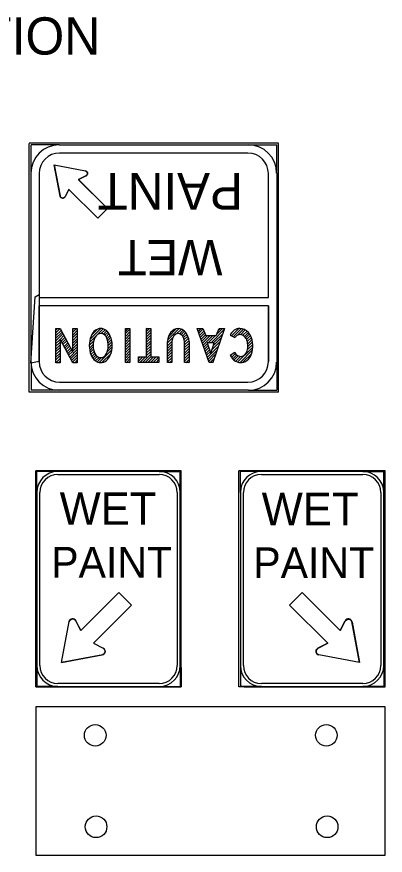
# Model space of a CAD drawing. Extents: x 1531.94 to 1538.58, y 1529.59 to 1539.32.
# Drawn here: x 1536.631 to 1537.698, y 1536.89 to 1539.32 of the extents above; entities that cross this region are included whole.
import ezdxf

# ---------------------------------------------------------------- set-up
doc = ezdxf.new("R2010")
doc.units = 0
for name, color, linetype in [('DETL-LINE', 7, 'Continuous'), ('DETL-TITL', 7, 'Continuous'), ('USER-BORD', 7, 'Continuous')]:
    doc.layers.add(name, color=color, linetype=linetype)

# ---------------------------------------------------------------- blocks, each defined once
blk = doc.blocks.new('EBK780')
at = {"layer": 'USER-BORD'}
blk.add_lwpolyline([(1.5, 0), (0.39, 1.65), (0.39, 0), (0, 0), (0, 2.4), (0.39, 2.4), (1.5, 0.75), (1.5, 2.4), (1.89, 2.4), (1.89, 0)], close=True, dxfattribs=at)
blk = doc.blocks.new('EBK790')
at = {"layer": 'USER-BORD'}
for centre, radius, start, end in [((1, 1.451), 0.943, 26.05051, 153.94949), ((1.477, 1.193), 1.484, 153.11255, 206.88745), ((1, 1.451), 0.593, 30.87343, 149.12656), ((0.523, 1.193), 1.484, 333.11255, 26.88745), ((1.477, 1.193), 1.134, 150.33396, 206.88745), ((0.523, 1.193), 1.134, 330.33396, 29.66604), ((1, 0.936), 0.593, 206.05051, 329.12657), ((1, 0.936), 0.943, 206.05051, 333.94949)]:
    blk.add_arc(centre, radius, start, end, dxfattribs=at)
blk = doc.blocks.new('EBK730')
at = {"layer": 'USER-BORD'}
blk.add_lwpolyline([(0.3996, 2.3977), (0.3996, 0), (0, 0), (0, 2.3977)], close=True, dxfattribs=at)
blk = doc.blocks.new('EBK840')
at = {"layer": 'USER-BORD'}
blk.add_lwpolyline([(1.1024, -0.0068), (0.7028, -0.0068), (0.7028, 1.9913), (0.0026, 1.9913), (0.0026, 2.3909), (1.8026, 2.3909), (1.8026, 1.9913), (1.1024, 1.9913)], close=True, dxfattribs=at)
blk = doc.blocks.new('EBK850')
at = {"layer": 'USER-BORD'}
for points in [[(0.001, 0.9), (0.001, 2.398), (0.401, 2.398), (0.401, 0.9)], [(1.501, 0.9), (1.501, 2.398), (1.901, 2.398), (1.901, 0.9)]]:
    blk.add_lwpolyline(points, dxfattribs=at)
for centre, radius, start, end in [((0.951, 0.951), 0.951, 183.08456, 356.91544), ((0.951, 0.9), 0.55, 180, 0)]:
    blk.add_arc(centre, radius, start, end, dxfattribs=at)
blk = doc.blocks.new('EBK650')
at = {"layer": 'USER-BORD'}
blk.add_lwpolyline([(1.6744, 0.479), (0.7349, 0.479), (0.4957, 0), (0, 0), (1.0352, 2.3825), (1.3681, 2.3825), (2.4033, 0), (1.9076, 0), (1.6684, 0.479)], dxfattribs=at)
blk.add_lwpolyline([(1.2017, 1.7541), (0.9085, 0.9938), (1.5306, 0.9938)], close=True, dxfattribs=at)
blk = doc.blocks.new('EBK670')
at = {"layer": 'USER-BORD'}
for p, q in [((1.582, 1.676), (1.964, 1.888)), ((1.981, 0.462), (1.569, 0.631)), ((1.981, 0.462), (1.981, 0.462))]:
    blk.add_line(p, q, dxfattribs=at)
for centre, radius, start, end in [((1.058, 1.338), 1.06, 31.25658, 163.71904), ((1.058, 1.338), 0.623, 32.82084, 158.25313), ((2.007, 1.189), 2.016, 167.21329, 185.68444), ((1.445, 1.229), 1.023, 160.60471, 209.69376), ((1.124, 1.121), 1.131, 186.67975, 270.86337), ((1.124, 1.121), 0.695, 215.04405, 285.81135), ((1.148, 0.961), 0.535, 288.00465, 321.8072), ((1.148, 0.961), 0.971, 269.58816, 329.07561)]:
    blk.add_arc(centre, radius, start, end, dxfattribs=at)

msp = doc.modelspace()

# ---------------------------------------------------------------- linework, layer by layer
at = {"layer": 'DETL-LINE'}
for p, q in [((1537.3887, 1538.9543), (1536.6672, 1538.9543)), ((1536.6672, 1538.2329), (1536.6672, 1538.953)), ((1536.754, 1538.949), (1536.6725, 1538.949)), ((1536.6725, 1538.8675), (1536.6725, 1538.949)), ((1536.754, 1538.949), (1537.3019, 1538.949)), ((1537.3019, 1538.949), (1537.3838, 1538.949)), ((1537.3838, 1538.8675), (1537.3838, 1538.949)), ((1537.3887, 1538.2329), (1537.3887, 1538.953)), ((1537.3005, 1538.9255), (1536.7553, 1538.9255)), ((1536.7398, 1538.891), (1536.7566, 1538.8011)), ((1536.7398, 1538.891), (1536.8298, 1538.8737)), ((1536.6725, 1538.3197), (1536.6725, 1538.8675)), ((1536.696, 1538.8662), (1536.696, 1538.5066)), ((1537.3599, 1538.5066), (1537.3599, 1538.8662)), ((1537.3838, 1538.8675), (1537.3838, 1538.3197)), ((1536.8102, 1538.8485), (1536.8315, 1538.8591)), ((1536.8102, 1538.848), (1536.894, 1538.7643)), ((1536.7824, 1538.8206), (1536.7713, 1538.7989)), ((1536.7824, 1538.8201), (1536.866, 1538.7365)), ((1536.866, 1538.7365), (1536.894, 1538.7643)), ((1536.696, 1538.5066), (1537.3599, 1538.5066)), ((1537.3599, 1538.4831), (1536.696, 1538.4831)), ((1536.696, 1538.321), (1536.696, 1538.4831)), ((1537.3599, 1538.4831), (1537.3599, 1538.321)), ((1537.3599, 1538.3209), (1537.3599, 1538.4831)), ((1536.7566, 1538.4167), (1536.7438, 1538.4038)), ((1536.7491, 1538.4167), (1536.7438, 1538.4113)), ((1536.7598, 1538.4113), (1536.7438, 1538.3959)), ((1536.7624, 1538.4065), (1536.7438, 1538.3879)), ((1536.7651, 1538.4012), (1536.7438, 1538.3799)), ((1536.804, 1538.4167), (1536.7934, 1538.406)), ((1536.7961, 1538.4167), (1536.7934, 1538.414)), ((1536.8063, 1538.4109), (1536.7934, 1538.3981)), ((1536.8063, 1538.4034), (1536.7934, 1538.3905)), ((1536.8745, 1538.4167), (1536.8435, 1538.3857)), ((1536.8647, 1538.4149), (1536.8479, 1538.3981)), ((1536.8816, 1538.4158), (1536.8647, 1538.3994)), ((1536.8869, 1538.4136), (1536.8758, 1538.4025)), ((1536.8918, 1538.4105), (1536.882, 1538.4007)), ((1536.8957, 1538.4065), (1536.8864, 1538.3972)), ((1536.8988, 1538.4021), (1536.89, 1538.3932)), ((1536.9528, 1538.4167), (1536.9458, 1538.4096)), ((1536.959, 1538.4149), (1536.9458, 1538.4021)), ((1536.959, 1538.4074), (1536.9458, 1538.3941)), ((1537.0158, 1538.4167), (1537.0064, 1538.4078)), ((1537.0078, 1538.4167), (1537.0064, 1538.4158)), ((1537.0197, 1538.4131), (1537.0064, 1538.3998)), ((1537.0197, 1538.4051), (1537.0064, 1538.3923)), ((1537.1012, 1538.4167), (1537.068, 1538.383)), ((1537.0928, 1538.4158), (1537.0702, 1538.3932)), ((1537.1079, 1538.4149), (1537.0941, 1538.4016)), ((1537.1128, 1538.4122), (1537.1021, 1538.4016)), ((1537.1172, 1538.4091), (1537.1074, 1538.3994)), ((1537.1212, 1538.4051), (1537.1118, 1538.3954)), ((1537.1242, 1538.4003), (1537.1145, 1538.3905)), ((1537.1562, 1538.4167), (1537.1548, 1538.4153)), ((1537.1641, 1538.4167), (1537.157, 1538.4091)), ((1537.1712, 1538.4158), (1537.1588, 1538.4034)), ((1537.1734, 1538.41), (1537.161, 1538.3976)), ((1537.1756, 1538.4047), (1537.1628, 1538.3919)), ((1537.2328, 1538.4149), (1537.1938, 1538.3755)), ((1537.2288, 1538.4029), (1537.2013, 1538.3755)), ((1537.2266, 1538.4167), (1537.2106, 1538.4007)), ((1537.219, 1538.4167), (1537.2159, 1538.4136)), ((1537.262, 1538.4127), (1537.2514, 1538.4021)), ((1537.274, 1538.4167), (1537.2527, 1538.3954)), ((1537.2815, 1538.4167), (1537.258, 1538.3927)), ((1537.2877, 1538.4149), (1537.2704, 1538.3976)), ((1537.293, 1538.4127), (1537.2793, 1538.3989)), ((1537.2979, 1538.4091), (1537.2855, 1538.3972)), ((1537.3019, 1538.4056), (1537.2904, 1538.3941)), ((1537.305, 1538.4012), (1537.2939, 1538.3897)), ((1536.7566, 1538.3852), (1536.7438, 1538.3724)), ((1536.7566, 1538.3773), (1536.7438, 1538.3644)), ((1536.7677, 1538.3963), (1536.7571, 1538.3852)), ((1536.7704, 1538.391), (1536.7598, 1538.3803)), ((1536.7735, 1538.3861), (1536.7624, 1538.375)), ((1536.7762, 1538.3808), (1536.7651, 1538.3702)), ((1536.7788, 1538.3759), (1536.7682, 1538.3649)), ((1536.8063, 1538.3954), (1536.7934, 1538.3826)), ((1536.8063, 1538.3874), (1536.7934, 1538.3746)), ((1536.8063, 1538.3799), (1536.7934, 1538.3671)), ((1536.8545, 1538.3812), (1536.8413, 1538.3679)), ((1536.8603, 1538.3945), (1536.8417, 1538.3764)), ((1536.9015, 1538.3967), (1536.8926, 1538.3879)), ((1536.9037, 1538.3914), (1536.8944, 1538.3817)), ((1536.9055, 1538.3852), (1536.8957, 1538.375)), ((1536.9068, 1538.3786), (1536.8962, 1538.3679)), ((1536.959, 1538.3994), (1536.9458, 1538.3861)), ((1536.959, 1538.3914), (1536.9458, 1538.3781)), ((1536.959, 1538.3839), (1536.9458, 1538.3706)), ((1536.959, 1538.3759), (1536.9458, 1538.3626)), ((1537.0197, 1538.3976), (1537.0064, 1538.3843)), ((1537.0197, 1538.3897), (1537.0064, 1538.3764)), ((1537.0197, 1538.3817), (1537.0064, 1538.3688)), ((1537.0826, 1538.3901), (1537.0676, 1538.375)), ((1537.0809, 1538.3803), (1537.0676, 1538.3671)), ((1537.1269, 1538.395), (1537.1163, 1538.3848)), ((1537.1287, 1538.3892), (1537.1167, 1538.3773)), ((1537.13, 1538.3826), (1537.1167, 1538.3693)), ((1537.1778, 1538.3989), (1537.165, 1538.3861)), ((1537.1836, 1538.3967), (1537.1668, 1538.3803)), ((1537.1912, 1538.3967), (1537.169, 1538.3746)), ((1537.1991, 1538.3967), (1537.1708, 1538.3688)), ((1537.2071, 1538.3967), (1537.1858, 1538.3755)), ((1537.2204, 1538.379), (1537.1974, 1538.356)), ((1537.2244, 1538.391), (1537.2009, 1538.3675)), ((1537.3081, 1538.3963), (1537.2966, 1538.3848)), ((1537.3107, 1538.391), (1537.2988, 1538.379)), ((1537.3125, 1538.3848), (1537.3001, 1538.3724)), ((1537.3138, 1538.3786), (1537.3001, 1538.3649)), ((1536.7566, 1538.3693), (1536.7438, 1538.3564)), ((1536.7566, 1538.3617), (1536.7438, 1538.3489)), ((1536.7566, 1538.3538), (1536.7438, 1538.3409)), ((1536.7815, 1538.3706), (1536.7708, 1538.36)), ((1536.7841, 1538.3657), (1536.7735, 1538.3547)), ((1536.7868, 1538.3604), (1536.7762, 1538.3498)), ((1536.7899, 1538.3555), (1536.7788, 1538.3445)), ((1536.8063, 1538.3564), (1536.7846, 1538.3343)), ((1536.8063, 1538.3719), (1536.7934, 1538.3591)), ((1536.8063, 1538.3639), (1536.7934, 1538.3511)), ((1536.8532, 1538.3719), (1536.8417, 1538.3604)), ((1536.8528, 1538.3639), (1536.8426, 1538.3533)), ((1536.8536, 1538.3569), (1536.8439, 1538.3471)), ((1536.9068, 1538.3551), (1536.87, 1538.3183)), ((1536.9077, 1538.3635), (1536.8931, 1538.3493)), ((1536.9077, 1538.3715), (1536.8957, 1538.3595)), ((1536.959, 1538.3679), (1536.9458, 1538.3547)), ((1536.959, 1538.36), (1536.9458, 1538.3471)), ((1536.959, 1538.3525), (1536.9458, 1538.3391)), ((1537.0197, 1538.3741), (1537.0064, 1538.3609)), ((1537.0197, 1538.3662), (1537.0064, 1538.3529)), ((1537.0197, 1538.3582), (1537.0064, 1538.3453)), ((1537.0809, 1538.3724), (1537.0676, 1538.3591)), ((1537.0809, 1538.3644), (1537.0676, 1538.3515)), ((1537.0809, 1538.3569), (1537.0676, 1538.3436)), ((1537.13, 1538.3746), (1537.1167, 1538.3617)), ((1537.13, 1538.3671), (1537.1167, 1538.3538)), ((1537.13, 1538.3591), (1537.1167, 1538.3458)), ((1537.1836, 1538.3737), (1537.173, 1538.3631)), ((1537.1858, 1538.3679), (1537.1752, 1538.3569)), ((1537.1876, 1538.3622), (1537.177, 1538.3511)), ((1537.1898, 1538.356), (1537.1792, 1538.3453)), ((1537.212, 1538.3551), (1537.185, 1538.3281)), ((1537.2164, 1538.3671), (1537.1938, 1538.3449)), ((1537.3143, 1538.3631), (1537.2704, 1538.3192)), ((1537.3138, 1538.3547), (1537.277, 1538.3179)), ((1537.3143, 1538.3711), (1537.2992, 1538.356)), ((1536.7566, 1538.3458), (1536.7438, 1538.3329)), ((1536.7566, 1538.3383), (1536.7438, 1538.3254)), ((1536.7566, 1538.3303), (1536.7442, 1538.3179)), ((1536.7925, 1538.3503), (1536.7815, 1538.3396)), ((1536.8063, 1538.3485), (1536.7872, 1538.3294)), ((1536.8063, 1538.3405), (1536.7899, 1538.3241)), ((1536.8063, 1538.3329), (1536.7925, 1538.3192)), ((1536.8554, 1538.3507), (1536.8461, 1538.3414)), ((1536.8576, 1538.3449), (1536.8483, 1538.3356)), ((1536.8603, 1538.3401), (1536.8514, 1538.3312)), ((1536.8643, 1538.3361), (1536.855, 1538.3268)), ((1536.8696, 1538.3334), (1536.8594, 1538.3232)), ((1536.8767, 1538.3325), (1536.8643, 1538.3201)), ((1536.9042, 1538.3445), (1536.878, 1538.3183)), ((1536.959, 1538.3445), (1536.9458, 1538.3312)), ((1536.959, 1538.3365), (1536.9458, 1538.3237)), ((1536.959, 1538.329), (1536.948, 1538.3179)), ((1536.9958, 1538.3347), (1536.9834, 1538.3223)), ((1536.9883, 1538.3347), (1536.9834, 1538.3299)), ((1537.0038, 1538.3347), (1536.9874, 1538.3183)), ((1537.0197, 1538.3427), (1536.9954, 1538.3183)), ((1537.0197, 1538.3347), (1537.0029, 1538.3183)), ((1537.0197, 1538.3507), (1537.0064, 1538.3374)), ((1537.0273, 1538.3347), (1537.0109, 1538.3183)), ((1537.0352, 1538.3347), (1537.0188, 1538.3183)), ((1537.0428, 1538.3343), (1537.0264, 1538.3183)), ((1537.0809, 1538.3489), (1537.0676, 1538.3356)), ((1537.0809, 1538.3409), (1537.0676, 1538.3281)), ((1537.0809, 1538.3334), (1537.0676, 1538.3201)), ((1537.13, 1538.3511), (1537.1167, 1538.3383)), ((1537.13, 1538.3436), (1537.1167, 1538.3303)), ((1537.13, 1538.3356), (1537.1167, 1538.3223)), ((1537.13, 1538.3276), (1537.1203, 1538.3179)), ((1537.192, 1538.3503), (1537.181, 1538.3396)), ((1537.1938, 1538.3445), (1537.1832, 1538.3338)), ((1537.208, 1538.3431), (1537.1872, 1538.3223)), ((1537.2036, 1538.3307), (1537.1912, 1538.3183)), ((1537.2536, 1538.3418), (1537.25, 1538.3378)), ((1537.2642, 1538.3445), (1537.2527, 1538.3329)), ((1537.2678, 1538.3401), (1537.2562, 1538.3285)), ((1537.2726, 1538.3374), (1537.2602, 1538.325)), ((1537.2788, 1538.3356), (1537.2651, 1538.3219)), ((1537.3116, 1538.3449), (1537.285, 1538.3183)), ((1536.6725, 1538.3197), (1536.6725, 1538.2382)), ((1536.7566, 1538.3223), (1536.7522, 1538.3179)), ((1536.8063, 1538.325), (1536.7992, 1538.3179)), ((1536.959, 1538.321), (1536.956, 1538.3179)), ((1537.0428, 1538.3268), (1537.0344, 1538.3183)), ((1537.0428, 1538.3188), (1537.0423, 1538.3183)), ((1537.0809, 1538.3254), (1537.0733, 1538.3179)), ((1537.13, 1538.3201), (1537.1278, 1538.3179)), ((1537.1996, 1538.3188), (1537.1991, 1538.3183)), ((1537.3838, 1538.3197), (1537.3838, 1538.2382)), ((1536.7553, 1538.2617), (1537.3005, 1538.2617)), ((1537.3887, 1538.2329), (1536.6672, 1538.2329)), ((1536.754, 1538.2382), (1536.6725, 1538.2382)), ((1537.3019, 1538.2382), (1536.754, 1538.2382)), ((1537.3019, 1538.2382), (1537.3838, 1538.2382)), ((1537.1077, 1538.0041), (1536.6862, 1538.0041)), ((1536.6862, 1537.3785), (1536.6862, 1538.0041)), ((1536.6894, 1537.942), (1536.6894, 1538.0027)), ((1536.75, 1538.0027), (1536.6894, 1538.0027)), ((1537.0439, 1538.0027), (1536.75, 1538.0027)), ((1536.75, 1537.9941), (1537.0439, 1537.9941)), ((1537.0439, 1538.0027), (1537.1045, 1538.0027)), ((1537.1045, 1537.942), (1537.1045, 1538.0027)), ((1537.1077, 1537.4341), (1537.1077, 1538.0041)), ((1537.6981, 1538.0041), (1537.2745, 1538.0041)), ((1537.2745, 1537.3785), (1537.2745, 1538.0041)), ((1537.2788, 1537.942), (1537.2788, 1538.0027)), ((1537.3394, 1538.0027), (1537.2788, 1538.0027)), ((1537.6332, 1538.0027), (1537.3394, 1538.0027)), ((1537.3394, 1537.9941), (1537.6332, 1537.9941)), ((1537.6332, 1538.0027), (1537.6938, 1538.0027)), ((1537.6662, 1538.003), (1537.6382, 1538.003)), ((1537.6662, 1538.003), (1537.6942, 1538.003)), ((1537.6938, 1537.942), (1537.6938, 1538.0027)), ((1537.6942, 1538.003), (1537.6942, 1537.8605)), ((1537.6981, 1537.3785), (1537.6981, 1538.0041)), ((1536.6894, 1537.942), (1536.6894, 1537.4405)), ((1536.6979, 1537.4405), (1536.6979, 1537.942)), ((1537.096, 1537.942), (1537.096, 1537.4405)), ((1537.1045, 1537.4405), (1537.1045, 1537.942)), ((1537.2788, 1537.942), (1537.2788, 1537.4405)), ((1537.2873, 1537.4405), (1537.2873, 1537.942)), ((1537.6854, 1537.942), (1537.6854, 1537.4405)), ((1537.6938, 1537.4405), (1537.6938, 1537.942)), ((1536.8167, 1537.5419), (1536.9269, 1537.6521)), ((1536.9269, 1537.6521), (1536.9634, 1537.6153)), ((1537.4578, 1537.6521), (1537.4213, 1537.6153)), ((1537.568, 1537.5419), (1537.4578, 1537.6521)), ((1536.8532, 1537.505), (1536.9634, 1537.6153)), ((1537.5315, 1537.505), (1537.4213, 1537.6153)), ((1536.7603, 1537.449), (1536.783, 1537.5674)), ((1536.8164, 1537.5415), (1536.8022, 1537.5699)), ((1537.5684, 1537.5415), (1537.5826, 1537.5699)), ((1537.624, 1537.449), (1537.6017, 1537.5674)), ((1536.8532, 1537.505), (1536.8816, 1537.4905)), ((1537.5315, 1537.505), (1537.5031, 1537.4905)), ((1536.7603, 1537.449), (1536.8788, 1537.4713)), ((1537.624, 1537.449), (1537.506, 1537.4713)), ((1536.6894, 1537.4405), (1536.6894, 1537.3799)), ((1537.1045, 1537.4405), (1537.1045, 1537.3799)), ((1537.1077, 1537.4341), (1537.1077, 1537.3785)), ((1537.2788, 1537.4405), (1537.2788, 1537.3799)), ((1537.6938, 1537.4405), (1537.6938, 1537.3799)), ((1536.75, 1537.3799), (1536.6894, 1537.3799)), ((1537.0439, 1537.3884), (1536.75, 1537.3884)), ((1536.75, 1537.3799), (1537.0439, 1537.3799)), ((1537.044, 1537.3884), (1537.0439, 1537.3884)), ((1537.0439, 1537.3799), (1537.1045, 1537.3799)), ((1537.3394, 1537.3799), (1537.2788, 1537.3799)), ((1537.6332, 1537.3884), (1537.3394, 1537.3884)), ((1537.3394, 1537.3799), (1537.6332, 1537.3799)), ((1537.6334, 1537.3884), (1537.6332, 1537.3884)), ((1537.6938, 1537.3799), (1537.6332, 1537.3799)), ((1536.6862, 1537.3785), (1537.1077, 1537.3785)), ((1537.2894, 1537.3785), (1537.2745, 1537.3785)), ((1537.2894, 1537.3785), (1537.6102, 1537.3785)), ((1537.6102, 1537.3785), (1537.6382, 1537.3785)), ((1537.6382, 1537.3785), (1537.6981, 1537.3785)), ((1537.6981, 1537.3209), (1536.6862, 1537.3209)), ((1536.6862, 1537.3209), (1536.6862, 1536.8905)), ((1536.8548, 1537.3209), (1536.8548, 1537.3209)), ((1537.0235, 1537.3209), (1537.0235, 1537.3209)), ((1537.1921, 1537.3209), (1537.1921, 1537.3209)), ((1537.3608, 1537.3209), (1537.3608, 1537.3209)), ((1537.5294, 1537.3209), (1537.5294, 1537.3209)), ((1537.6981, 1536.8905), (1537.6981, 1537.3209)), ((1536.6862, 1536.8905), (1537.6981, 1536.8905))]:
    msp.add_line(p, q, dxfattribs=at)
for points in [[(1536.8315, 1538.8591), (1536.8102, 1538.8485), (1536.894, 1538.7643), (1536.866, 1538.7365), (1536.7824, 1538.8201), (1536.7713, 1538.7989), (1536.767, 1538.7951), (1536.7619, 1538.795), (1536.7583, 1538.7974), (1536.7567, 1538.8009), (1536.7398, 1538.891), (1536.8298, 1538.8737), (1536.8331, 1538.8722), (1536.8356, 1538.8684), (1536.8357, 1538.8642)], [(1536.696, 1538.321), (1536.6724, 1538.3165), (1536.685, 1538.5091), (1536.696, 1538.516)], [(1536.9269, 1537.6521), (1536.9634, 1537.6153), (1536.8532, 1537.505), (1536.8816, 1537.4905), (1536.8857, 1537.4864), (1536.887, 1537.4805), (1536.8851, 1537.4755), (1536.88, 1537.4717), (1536.7603, 1537.449), (1536.783, 1537.5674), (1536.786, 1537.5728), (1536.794, 1537.5755), (1536.799, 1537.5735), (1536.8026, 1537.5689), (1536.8164, 1537.5415)], [(1537.4213, 1537.6153), (1537.4395, 1537.6337), (1537.4578, 1537.6521), (1537.568, 1537.5419), (1537.5826, 1537.5699), (1537.5887, 1537.5751), (1537.5968, 1537.5741), (1537.5993, 1537.5718), (1537.602, 1537.5658), (1537.624, 1537.449), (1537.506, 1537.4713), (1537.5019, 1537.4731), (1537.4978, 1537.4793), (1537.4985, 1537.4856), (1537.5019, 1537.4897), (1537.5315, 1537.505)]]:
    msp.add_lwpolyline(points, close=True, dxfattribs=at)
for centre in [(1536.8585, 1537.238), (1537.5277, 1537.238), (1536.8608, 1536.9729), (1537.53, 1536.9729)]:
    msp.add_circle(centre, 0.0313, dxfattribs=at)
for centre, radius, start, end in [((1536.7541, 1538.8675), 0.0818, 90, 180), ((1537.3018, 1538.8675), 0.0818, 0, 90), ((1536.7553, 1538.8662), 0.0593, 90, 180), ((1537.3006, 1538.8662), 0.0593, 0, 90), ((1536.8282, 1538.8662), 0.00776, 297, 79.2603), ((1536.7643, 1538.8023), 0.00776, 190.7397, 333), ((1536.7541, 1538.3197), 0.0818, 180, 270), ((1536.7553, 1538.3209), 0.0593, 180, 270), ((1537.3006, 1538.3209), 0.0593, 270, 0), ((1537.3018, 1538.3197), 0.0818, 270, 0), ((1536.7499, 1537.9421), 0.0606, 90, 180), ((1536.7499, 1537.9421), 0.0519, 90, 180), ((1537.044, 1537.9421), 0.0606, 0, 90), ((1537.044, 1537.9421), 0.0519, 0, 90), ((1537.3392, 1537.9421), 0.0606, 90, 180), ((1537.3392, 1537.9421), 0.0519, 90, 180), ((1537.6333, 1537.9421), 0.0606, 0, 90), ((1537.6333, 1537.9421), 0.0519, 0, 90), ((1536.7929, 1537.5653), 0.0102, 27, 169.2603), ((1537.5917, 1537.5653), 0.0102, 10.7397, 153), ((1536.8768, 1537.4814), 0.0102, 280.7397, 63), ((1537.5078, 1537.4814), 0.0102, 117, 259.2603), ((1536.7499, 1537.4403), 0.0606, 180, 270), ((1536.7499, 1537.4403), 0.0519, 180, 270), ((1537.044, 1537.4403), 0.0606, 270, 0), ((1537.044, 1537.4403), 0.0519, 270, 0), ((1537.3392, 1537.4403), 0.0606, 180, 270), ((1537.3392, 1537.4403), 0.0519, 180, 270), ((1537.6333, 1537.4403), 0.0606, 270, 0), ((1537.6333, 1537.4403), 0.0519, 270, 0)]:
    msp.add_arc(centre, radius, start, end, dxfattribs=at)

# ---------------------------------------------------------------- block references
at = {"layer": 'DETL-LINE', "xscale": 0.03292910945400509, "yscale": 0.04116138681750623, "rotation": 179.99999999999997}
for name, p in [('EBK780', (1536.8063, 1538.4167)), ('EBK790', (1536.9072, 1538.4167)), ('EBK730', (1536.959, 1538.4167)), ('EBK840', (1537.0428, 1538.4167)), ('EBK850', (1537.13, 1538.4167)), ('EBK650', (1537.2332, 1538.4167)), ('EBK670', (1537.3143, 1538.4167))]:
    msp.add_blockref(name, p, dxfattribs=at)

# ---------------------------------------------------------------- texts
at = {"layer": 'DETL-LINE'}
for s, height, rotation, p in [('PAINT', 0.10696, 180, (1537.2862, 1538.8679)), ('WET', 0.10182, 180, (1537.2268, 1538.6733)), ('WET', 0.09438, 360, (1536.7553, 1537.8481)), ('WET', 0.09438, 360, (1537.3404, 1537.8467)), ('PAINT', 0.08889, 360, (1536.7309, 1537.6952)), ('PAINT', 0.08889, 360, (1537.316, 1537.6938))]:
    msp.add_text(s, height=height, rotation=rotation, dxfattribs=at).set_placement(p)
at = {"layer": 'DETL-TITL'}
msp.add_text('TEMPORARY TRAFFIC CONTROL TYPICAL APPLICATION', height=0.108, dxfattribs=at).set_placement((1532.925, 1539.2108))

doc.saveas('drawing.dxf')
